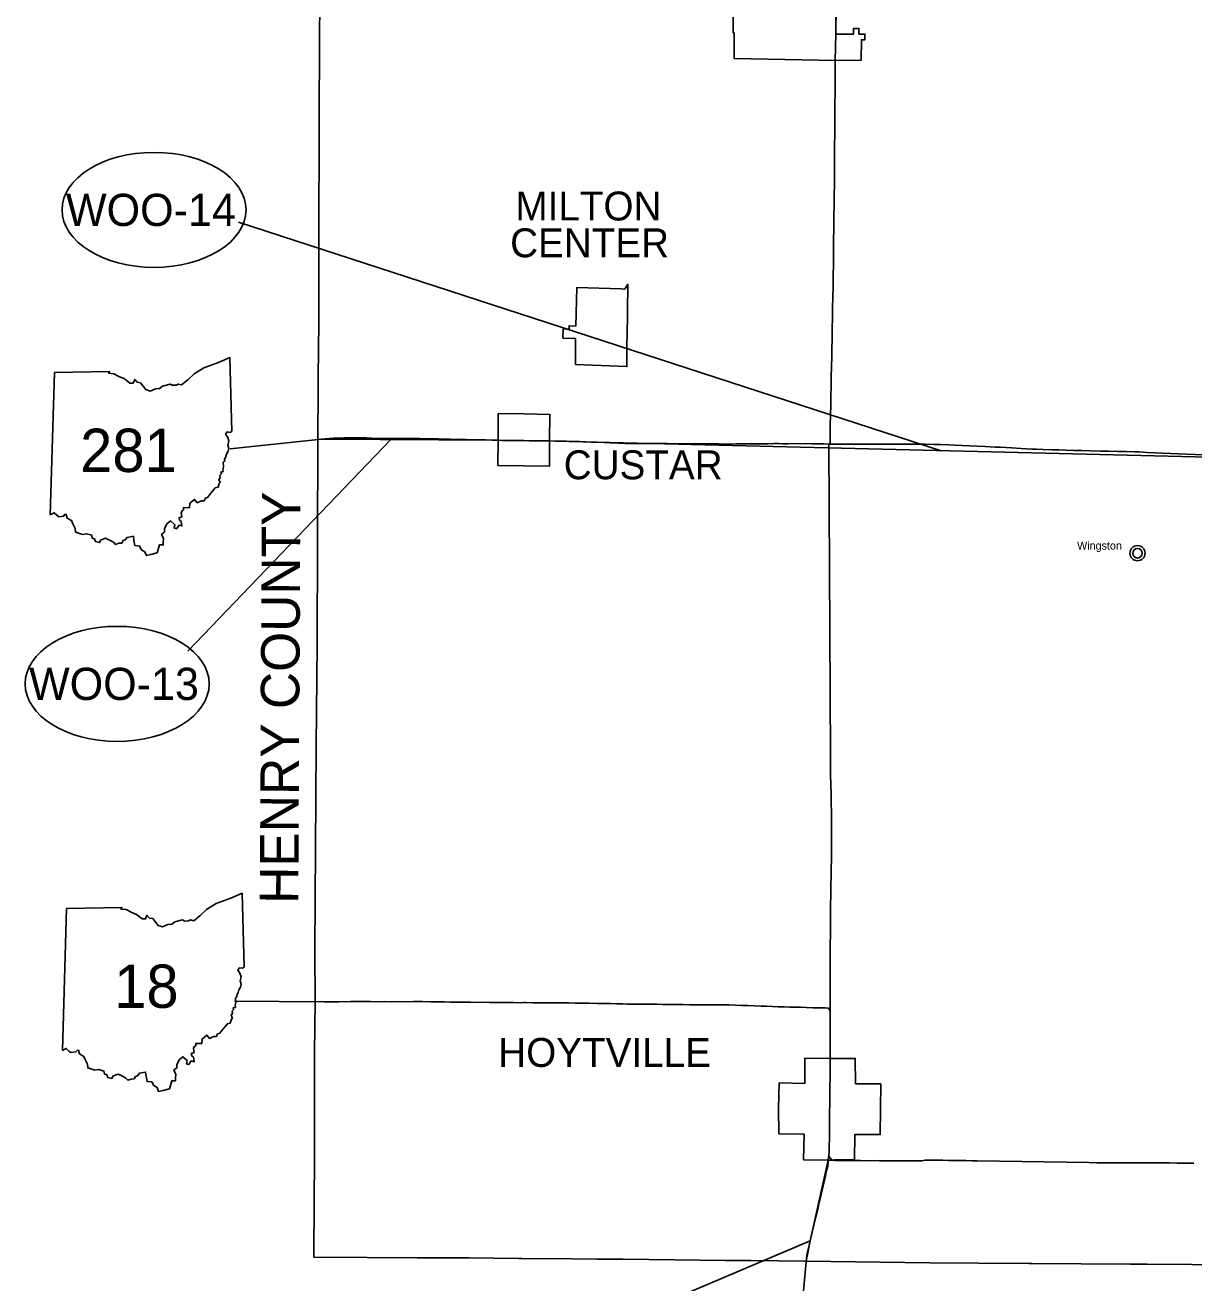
# Model space of a CAD drawing. Extents: x 0 to 851, y 0 to 440.
# Drawn here: x 180.9 to 282.5, y 84.4 to 193.8 of the extents above; entities that cross this region are included whole.
import ezdxf

# ---------------------------------------------------------------- set-up
doc = ezdxf.new("R2010")
doc.units = 0
for name, color, linetype in [('DV_X_Corp_Line', 7, 'Continuous'), ('GM_X_Adjacent_County_Text', 7, 'Continuous'), ('GM_X_Corporation_Text', 7, 'Continuous'), ('GM_X_County', 7, 'Continuous'), ('GM_X_State_Route', 7, 'Continuous'), ('PV_P_Text', 7, 'Continuous'), ('RD_P_Fence', 7, 'Continuous'), ('SH_Data', 7, 'Continuous')]:
    doc.layers.add(name, color=color, linetype=linetype)

msp = doc.modelspace()

# ---------------------------------------------------------------- linework, layer by layer
at = {"layer": 'DV_X_Corp_Line'}
msp.add_lwpolyline([(251.36, 195.22), (251.34, 192.98), (252.2, 192.97), (252.88, 192.97), (252.88, 193.47), (253.35, 193.47), (253.35, 192.97), (253.87, 192.97), (253.87, 192.48), (253.56, 192.48), (253.55, 190.72), (251.32, 190.68), (246.9, 190.76), (242.49, 190.84), (242.51, 193.08), (242.42, 193.08), (242.46, 199.73)], dxfattribs=at)
for points in [[(228.7, 164.24), (228.7, 164.75), (228.7, 165.17), (228.7, 165.75), (228.7, 166.02), (228.69, 166.5), (227.61, 166.54), (227.64, 167.35), (228.14, 167.33), (228.15, 167.61), (228.73, 167.58), (228.81, 170.94), (232.68, 170.82), (232.98, 170.81), (233.26, 171.23), (233.19, 166.54), (233.18, 166.34), (233.17, 164.06)], [(221.95, 155.46), (221.98, 157.7), (221.99, 160), (224.25, 159.96), (226.47, 159.9), (226.45, 157.66), (226.43, 155.4), (224.18, 155.44)], [(246.38, 97.35), (246.35, 99.6), (246.42, 101.78), (248.63, 101.73), (248.65, 103.95), (250.89, 103.92), (253.03, 103.91), (253.05, 101.71), (255.24, 101.7), (255.2, 97.3), (253, 97.31), (252.97, 95.09), (252.52, 95.1), (252.08, 95.1), (251.58, 95.1), (251.28, 95.1), (251.23, 95.11), (251.15, 95.08), (250.74, 95.08), (248.54, 95.11), (248.6, 97.32)]]:
    msp.add_lwpolyline(points, close=True, dxfattribs=at)
for radius in [0.658, 0.417]:
    msp.add_circle((277.57, 147.84), radius, dxfattribs=at)
at = {"layer": 'GM_X_County'}
msp.add_lwpolyline([(286.18, 85.96), (278.4, 86.02), (277.29, 86.03), (276.96, 86.03), (268.38, 86.08), (268.13, 86.08), (263.75, 86.11), (259.48, 86.15), (248.77, 86.3), (243.96, 86.35), (241.7, 86.35), (237.33, 86.41), (232.85, 86.45), (230.6, 86.47), (228.39, 86.49), (224.05, 86.53), (223.76, 86.53), (219.47, 86.57), (214.94, 86.59), (210.58, 86.62), (205.96, 86.64), (205.96, 86.99), (206.01, 95.47), (206, 99.97), (206, 104.43), (206.08, 108.84), (206.03, 113.3), (206.09, 122.17), (206.15, 131.08), (206.23, 139.92), (206.27, 148.79), (206.3, 157.72), (206.37, 166.56), (206.38, 166.88), (206.38, 175.5), (206.38, 175.64), (206.41, 184.56), (206.45, 193.37), (206.48, 194.94)], dxfattribs=at)
at = {"layer": 'GM_X_State_Route'}
for points in [[(251.33, 192.99), (251.33, 193.74), (251.35, 194.49), (251.36, 195.22), (251.36, 195.6), (251.36, 196.41), (251.37, 197.3), (251.38, 198.22), (251.39, 199.02), (251.39, 199.66), (251.39, 199.83)], [(251.28, 190.69), (251.33, 192.99)], [(250.85, 157.33), (250.85, 157.94), (250.86, 158.93), (250.88, 159.84), (250.9, 160.73), (250.91, 161.5), (250.92, 162.36), (250.93, 163.18), (250.96, 164.08), (250.98, 164.92), (251, 165.75), (251.01, 166.24), (251.02, 166.76), (251.03, 167.36), (251.04, 168.32), (251.06, 169.16), (251.07, 170.1), (251.1, 171.04), (251.12, 172), (251.13, 172.91), (251.14, 173.71), (251.15, 174.57), (251.15, 175.15), (251.16, 175.95), (251.18, 177.11), (251.19, 178.08), (251.2, 178.96), (251.21, 179.95), (251.21, 180.98), (251.21, 181.82), (251.22, 182.76), (251.23, 183.5), (251.24, 184.06), (251.28, 190.65), (251.28, 190.69)], [(198.67, 156.91), (206.63, 157.76), (206.95, 157.79), (207.3, 157.81), (207.67, 157.83), (208.11, 157.84), (208.56, 157.86), (208.89, 157.86), (209.48, 157.87), (209.95, 157.87), (210.53, 157.87), (211.4, 157.81), (212.2, 157.81), (212.97, 157.81), (213.76, 157.8), (214.46, 157.8), (215.21, 157.8), (215.82, 157.79), (216.44, 157.77), (216.77, 157.77)], [(216.77, 157.77), (216.93, 157.76), (217.55, 157.75), (217.82, 157.75)], [(217.82, 157.75), (218.07, 157.74), (218.42, 157.74)], [(218.42, 157.74), (218.56, 157.74), (219.21, 157.73), (219.64, 157.71), (219.82, 157.71)], [(219.82, 157.71), (220.26, 157.69), (220.87, 157.69), (221.44, 157.67), (221.9, 157.66), (221.92, 157.66)], [(221.92, 157.66), (221.93, 157.66), (222.32, 157.65), (222.71, 157.65), (222.72, 157.65)], [(222.72, 157.65), (222.74, 157.65), (223.17, 157.64), (223.18, 157.64), (223.66, 157.64), (223.69, 157.64), (224.12, 157.63), (224.12, 157.63)], [(224.12, 157.63), (224.21, 157.63), (224.68, 157.62), (225.22, 157.62), (225.64, 157.61), (226.09, 157.61), (226.3, 157.6), (226.3, 157.6)], [(226.3, 157.6), (226.49, 157.6), (226.97, 157.59), (227.51, 157.58), (227.91, 157.57), (228.46, 157.56), (229.04, 157.54), (229.6, 157.52), (230.08, 157.5), (230.59, 157.48), (231.19, 157.46), (231.72, 157.44), (232.43, 157.42), (233.02, 157.39), (233.64, 157.38), (234.53, 157.38), (235.25, 157.38), (235.95, 157.37), (236.66, 157.37), (237.35, 157.36), (237.96, 157.36), (238.61, 157.36), (239.26, 157.35), (239.93, 157.35), (240.58, 157.34), (241.17, 157.34), (241.76, 157.33), (241.96, 157.33), (242.21, 157.33), (242.65, 157.34), (243.21, 157.34), (243.78, 157.35), (244.29, 157.35), (244.91, 157.36), (245.47, 157.36), (245.98, 157.37), (246.35, 157.37), (246.66, 157.36), (247.17, 157.36), (248.7, 157.37), (249.26, 157.35), (249.77, 157.34), (250.29, 157.34), (250.85, 157.33)], [(250.85, 108.05), (250.86, 108.35), (250.85, 109.1), (250.86, 109.87), (250.85, 110.71), (250.86, 111.38), (250.85, 112.22), (250.85, 112.71), (250.86, 113.85), (250.87, 114.68), (250.88, 115.63), (250.88, 116.45), (250.89, 117.27), (250.9, 118.08), (250.91, 118.97), (250.93, 119.72), (250.94, 120.49), (250.96, 121.21), (250.96, 121.79), (250.97, 122.31), (250.97, 123.15), (250.96, 123.99), (250.96, 124.66), (250.95, 125.38), (250.93, 126.09), (250.92, 126.93), (250.9, 127.76), (250.89, 128.54), (250.88, 129.53), (250.88, 130.21), (250.73, 157.32)], [(250.85, 157.33), (251.35, 157.32), (251.92, 157.33), (252.58, 157.32), (253.12, 157.32), (253.59, 157.32), (254.15, 157.32), (254.72, 157.31), (255.2, 157.32), (255.76, 157.31), (256.3, 157.31), (256.8, 157.31), (257.33, 157.31), (258.03, 157.31), (258.55, 157.31), (259.13, 157.31), (259.93, 157.29)], [(259.93, 157.29), (260.45, 157.28), (261.18, 157.25), (261.69, 157.23), (262.32, 157.2), (263, 157.17), (263.64, 157.14), (264.33, 157.11), (265.19, 157.07), (265.62, 157.05), (266.62, 157), (267.46, 156.94), (267.93, 156.92), (268.38, 156.89), (268.8, 156.88), (269.36, 156.86), (270.18, 156.84), (270.74, 156.82), (271.35, 156.8), (272, 156.78), (272.7, 156.77), (273.43, 156.75), (274.37, 156.72), (275.06, 156.7), (275.82, 156.68), (276.58, 156.67), (277.35, 156.64), (277.72, 156.64), (278.4, 156.61), (279.04, 156.58), (279.69, 156.55), (280.44, 156.52), (291.12, 156.07)], [(250.88, 130.21), (250.88, 130.3), (250.88, 130.66)], [(199.06, 108.88), (206.83, 108.84), (208.15, 108.83), (209.15, 108.85), (209.9, 108.85), (210.42, 108.85), (210.89, 108.85), (211.47, 108.84), (212.13, 108.85), (212.74, 108.84), (213.27, 108.85), (213.88, 108.84), (214.61, 108.85), (215.39, 108.85), (216.11, 108.84), (216.73, 108.83), (217.32, 108.83), (217.84, 108.82), (218.51, 108.82), (219.05, 108.81), (219.58, 108.8), (220.15, 108.79), (220.7, 108.8), (221.22, 108.79), (221.86, 108.78), (222.56, 108.77), (223.31, 108.77), (224.03, 108.76), (224.19, 108.77), (224.38, 108.77), (225.03, 108.76), (225.77, 108.76), (226.15, 108.75), (226.75, 108.74), (227.42, 108.74), (228.12, 108.74), (228.68, 108.73), (229.22, 108.72), (229.89, 108.71), (230.61, 108.7), (230.94, 108.69), (231.19, 108.69), (231.74, 108.68), (232.26, 108.66), (232.81, 108.66), (233.19, 108.64), (233.26, 108.64), (233.84, 108.63), (234.29, 108.63), (234.83, 108.63), (235.32, 108.63), (235.79, 108.62), (236.28, 108.61), (236.89, 108.61), (237.52, 108.6), (238.04, 108.59), (238.65, 108.58), (239.18, 108.58), (239.74, 108.58), (240.21, 108.57), (240.73, 108.57), (241.27, 108.57), (241.74, 108.57), (242.03, 108.56), (242.61, 108.54), (243.15, 108.52), (243.68, 108.51), (244.28, 108.48), (244.83, 108.47), (245.31, 108.45), (245.82, 108.43), (246.33, 108.41), (246.86, 108.4), (247.3, 108.38), (247.75, 108.37), (248.26, 108.36), (248.76, 108.34), (249.35, 108.32), (249.83, 108.31), (250.37, 108.3), (250.64, 108.28), (250.69, 108.27), (250.73, 108.23), (250.79, 108.14), (250.85, 108.05)], [(250.85, 108.05), (250.86, 107.61), (250.86, 107.03), (250.85, 106.46), (250.85, 105.9), (250.86, 105.4), (250.85, 104.94), (250.86, 104.41), (250.86, 103.85)], [(250.85, 102.97), (250.85, 102.75), (250.84, 102.2), (250.83, 101.55), (250.83, 100.94), (250.82, 100.67)], [(250.86, 103.85), (250.86, 103.85), (250.86, 103.33), (250.85, 102.97)], [(250.82, 100.67), (250.82, 100.67), (250.82, 100.64), (250.82, 100.56), (250.81, 100.1), (250.81, 99.98), (250.81, 99.71), (250.8, 99.47), (250.8, 99.44), (250.8, 99.44)], [(250.79, 98.55), (250.79, 98.49), (250.79, 98.4), (250.79, 97.9), (250.78, 97.39), (250.78, 97.23)], [(250.8, 99.44), (250.8, 99.35), (250.79, 98.91), (250.79, 98.55)], [(250.78, 97.23), (250.78, 97.23), (250.78, 96.86), (250.77, 96.33), (250.76, 96.06), (250.75, 95.85), (250.72, 95.47)], [(248.09, 79.05), (248.82, 86.84), (248.96, 87.39), (249.11, 88.06), (249.29, 88.82), (249.45, 89.52), (249.59, 90.14), (249.76, 90.82), (249.9, 91.43), (250.05, 92.09), (250.23, 92.85), (250.4, 93.57), (250.54, 94.16), (250.63, 94.54), (250.64, 94.64), (250.66, 94.81), (250.68, 95.06), (250.72, 95.47)], [(250.72, 95.47), (250.79, 95.34), (250.85, 95.25), (250.92, 95.18), (250.99, 95.12), (251.06, 95.06), (251.23, 95.05)], [(251.23, 95.05), (251.58, 95.04), (252.08, 95.04), (252.1, 95.04), (252.11, 95.04)], [(252.11, 95.04), (252.58, 95.04), (252.98, 95.04), (252.98, 95.04)], [(252.98, 95.04), (253.01, 95.04), (253.49, 95.03), (253.98, 95), (254.61, 95.04), (255.13, 95.02), (255.56, 95.02), (256.05, 95.02), (256.45, 95.01), (256.86, 95.02), (257.38, 95.02), (257.94, 95.02), (258.47, 95.01), (258.72, 95.01), (258.82, 95.02), (258.96, 95.05), (259.09, 95.07), (259.2, 95.07), (259.57, 95.06), (260.12, 95.06), (260.65, 95.06), (261.15, 95.05), (261.64, 95.04), (262.12, 95.03), (262.65, 95.03), (263.16, 95.02), (263.62, 95.01), (275.27, 94.84)], [(274.04, 94.85), (274.64, 94.85), (275.27, 94.84), (275.93, 94.84), (276.62, 94.85), (277.31, 94.85)], [(277.31, 94.85), (277.92, 94.85), (278.59, 94.85), (279.18, 94.84), (279.75, 94.83), (280.34, 94.83), (281.02, 94.82), (281.57, 94.81), (282.46, 94.81)]]:
    msp.add_lwpolyline(points, dxfattribs=at)
at = {"layer": 'PV_P_Text'}
for p, q in [((183.04, 151.18), (183.39, 163.55)), ((183.04, 151.18), (183.39, 163.55)), ((184.11, 104.59), (184.46, 116.96)), ((184.11, 104.59), (184.46, 116.96))]:
    msp.add_line(p, q, dxfattribs=at)
for points in [[(183.39, 163.55), (188.19, 163.63), (188.11, 163.48), (188.57, 163.45), (189.05, 163.18), (189.45, 163.02), (189.95, 162.62), (190.25, 162.63), (190.38, 162.95), (190.6, 162.7), (190.88, 162.66), (191.34, 162.07), (191.73, 161.94), (192.19, 162.14), (192.54, 162.17), (192.79, 162.37), (193.45, 162.55), (193.63, 162.44), (193.98, 162.46), (194.16, 162.54), (194.46, 162.47), (195, 162.92), (195.55, 163.45), (196.4, 163.95), (197.66, 164.43), (198.66, 164.85), (198.81, 158.43)], [(183.39, 163.55), (188.19, 163.63), (188.11, 163.48), (188.57, 163.45), (189.05, 163.18), (189.45, 163.02), (189.95, 162.62), (190.25, 162.63), (190.38, 162.95), (190.6, 162.7), (190.88, 162.66), (191.34, 162.07), (191.73, 161.94), (192.19, 162.14), (192.54, 162.17), (192.79, 162.37), (193.45, 162.55), (193.63, 162.44), (193.98, 162.46), (194.16, 162.54), (194.46, 162.47), (195, 162.92), (195.55, 163.45), (196.4, 163.95), (197.66, 164.43), (198.66, 164.85), (198.81, 158.43)], [(198.81, 158.43), (198.66, 158.34), (198.43, 158.38), (198.28, 158.2), (198.47, 157.9), (198.56, 157.58), (198.48, 157.23), (198.56, 156.95), (198.5, 156.7), (198.36, 156.46), (198.31, 156.24), (198.19, 155.99), (198.2, 155.86), (198.08, 155.75), (198.1, 155.35), (198.04, 155.13), (198.06, 154.94), (197.87, 154.89), (197.91, 154.73), (197.79, 154.6), (197.82, 154.39), (197.68, 154.26), (197.82, 153.99), (197.71, 153.9), (197.62, 153.58), (197.38, 153.51), (196.89, 152.91), (196.72, 152.68), (196.52, 152.63), (196.42, 152.4), (196.18, 152.39), (195.82, 152.23), (195.58, 152.51), (195.17, 152.18), (195.13, 151.79), (194.61, 151.8), (194.63, 151.61), (194.52, 151.55), (194.41, 151.36), (194.47, 151.01), (194.23, 150.92), (194.26, 150.72), (194.41, 150.6), (194.48, 150.21), (194.23, 150.29), (194.02, 149.96), (193.8, 150.04), (193.87, 150.31), (193.5, 150.65), (193.16, 150.38), (192.98, 149.96), (192.98, 149.67), (192.72, 149.5), (192.88, 149.1), (192.85, 148.82), (192.86, 148.56), (192.54, 148.57), (192.34, 147.86)], [(198.81, 158.43), (198.66, 158.34), (198.43, 158.38), (198.28, 158.2), (198.47, 157.9), (198.56, 157.58), (198.48, 157.23), (198.56, 156.95), (198.5, 156.7), (198.36, 156.46), (198.31, 156.24), (198.19, 155.99), (198.2, 155.86), (198.08, 155.75), (198.1, 155.35), (198.04, 155.13), (198.06, 154.94), (197.87, 154.89), (197.91, 154.73), (197.79, 154.6), (197.82, 154.39), (197.68, 154.26), (197.82, 153.99), (197.71, 153.9), (197.62, 153.58), (197.38, 153.51), (196.89, 152.91), (196.72, 152.68), (196.52, 152.63), (196.42, 152.4), (196.18, 152.39), (195.82, 152.23), (195.58, 152.51), (195.17, 152.18), (195.13, 151.79), (194.61, 151.8), (194.63, 151.61), (194.52, 151.55), (194.41, 151.36), (194.47, 151.01), (194.23, 150.92), (194.26, 150.72), (194.41, 150.6), (194.48, 150.21), (194.23, 150.29), (194.02, 149.96), (193.8, 150.04), (193.87, 150.31), (193.5, 150.65), (193.16, 150.38), (192.98, 149.96), (192.98, 149.67), (192.72, 149.5), (192.88, 149.1), (192.85, 148.82), (192.86, 148.56), (192.54, 148.57), (192.34, 147.86)], [(192.34, 147.86), (191.78, 147.72), (191.39, 147.64), (191.25, 147.96), (190.98, 148.13), (190.8, 148.46), (190.4, 148.5), (190.3, 148.95), (190.26, 149.31), (189.71, 149.22), (189.56, 149), (189.37, 148.94), (189.26, 148.72), (188.99, 148.7), (188.71, 148.59), (188.52, 148.81), (188.06, 149.03), (187.85, 149.14), (187.41, 148.97), (187.32, 148.76), (186.97, 148.85), (186.89, 149.08), (186.68, 149.15), (186.64, 149.4), (186.19, 149.53), (185.84, 149.48), (185.24, 149.68), (185.2, 150), (184.99, 150.4), (184.89, 150.67), (184.5, 150.88), (184.43, 151.21), (184.3, 151.2), (184.19, 151.06), (183.77, 151), (183.6, 151.14), (183.36, 151.36), (183.04, 151.18)], [(192.34, 147.86), (191.78, 147.72), (191.39, 147.64), (191.25, 147.96), (190.98, 148.13), (190.8, 148.46), (190.4, 148.5), (190.3, 148.95), (190.26, 149.31), (189.71, 149.22), (189.56, 149), (189.37, 148.94), (189.26, 148.72), (188.99, 148.7), (188.71, 148.59), (188.52, 148.81), (188.06, 149.03), (187.85, 149.14), (187.41, 148.97), (187.32, 148.76), (186.97, 148.85), (186.89, 149.08), (186.68, 149.15), (186.64, 149.4), (186.19, 149.53), (185.84, 149.48), (185.24, 149.68), (185.2, 150), (184.99, 150.4), (184.89, 150.67), (184.5, 150.88), (184.43, 151.21), (184.3, 151.2), (184.19, 151.06), (183.77, 151), (183.6, 151.14), (183.36, 151.36), (183.04, 151.18)], [(184.46, 116.96), (189.26, 117.04), (189.18, 116.9), (189.63, 116.86), (190.12, 116.6), (190.52, 116.43), (191.02, 116.04), (191.32, 116.04), (191.44, 116.37), (191.67, 116.12), (191.94, 116.07), (192.41, 115.48), (192.8, 115.35), (193.26, 115.56), (193.61, 115.59), (193.86, 115.79), (194.52, 115.96), (194.7, 115.86), (195.05, 115.88), (195.22, 115.95), (195.53, 115.89), (196.06, 116.34), (196.62, 116.87), (197.46, 117.37), (198.73, 117.84), (199.73, 118.27), (199.88, 111.85)], [(184.46, 116.96), (189.26, 117.04), (189.18, 116.9), (189.63, 116.86), (190.12, 116.6), (190.52, 116.43), (191.02, 116.04), (191.32, 116.04), (191.44, 116.37), (191.67, 116.12), (191.94, 116.07), (192.41, 115.48), (192.8, 115.35), (193.26, 115.56), (193.61, 115.59), (193.86, 115.79), (194.52, 115.96), (194.7, 115.86), (195.05, 115.88), (195.22, 115.95), (195.53, 115.89), (196.06, 116.34), (196.62, 116.87), (197.46, 117.37), (198.73, 117.84), (199.73, 118.27), (199.88, 111.85)], [(199.88, 111.85), (199.73, 111.76), (199.5, 111.8), (199.34, 111.62), (199.53, 111.32), (199.63, 111), (199.55, 110.65), (199.62, 110.36), (199.57, 110.12), (199.43, 109.88), (199.38, 109.65), (199.25, 109.41), (199.26, 109.27), (199.15, 109.17), (199.17, 108.77), (199.11, 108.54), (199.13, 108.35), (198.94, 108.3), (198.98, 108.14), (198.86, 108.02), (198.89, 107.81), (198.75, 107.67), (198.88, 107.4), (198.78, 107.32), (198.69, 106.99), (198.44, 106.93), (197.96, 106.33), (197.78, 106.1), (197.59, 106.04), (197.48, 105.81), (197.24, 105.81), (196.88, 105.65), (196.65, 105.93), (196.24, 105.59), (196.2, 105.21), (195.68, 105.22), (195.7, 105.02), (195.58, 104.97), (195.48, 104.77), (195.54, 104.42), (195.3, 104.34), (195.33, 104.13), (195.48, 104.01), (195.55, 103.63), (195.29, 103.7), (195.08, 103.38), (194.87, 103.45), (194.94, 103.73), (194.57, 104.06), (194.23, 103.8), (194.05, 103.37), (194.04, 103.09), (193.79, 102.92), (193.95, 102.51), (193.92, 102.24), (193.93, 101.97), (193.6, 101.98), (193.41, 101.27)], [(199.88, 111.85), (199.73, 111.76), (199.5, 111.8), (199.34, 111.62), (199.53, 111.32), (199.63, 111), (199.55, 110.65), (199.62, 110.36), (199.57, 110.12), (199.43, 109.88), (199.38, 109.65), (199.25, 109.41), (199.26, 109.27), (199.15, 109.17), (199.17, 108.77), (199.11, 108.54), (199.13, 108.35), (198.94, 108.3), (198.98, 108.14), (198.86, 108.02), (198.89, 107.81), (198.75, 107.67), (198.88, 107.4), (198.78, 107.32), (198.69, 106.99), (198.44, 106.93), (197.96, 106.33), (197.78, 106.1), (197.59, 106.04), (197.48, 105.81), (197.24, 105.81), (196.88, 105.65), (196.65, 105.93), (196.24, 105.59), (196.2, 105.21), (195.68, 105.22), (195.7, 105.02), (195.58, 104.97), (195.48, 104.77), (195.54, 104.42), (195.3, 104.34), (195.33, 104.13), (195.48, 104.01), (195.55, 103.63), (195.29, 103.7), (195.08, 103.38), (194.87, 103.45), (194.94, 103.73), (194.57, 104.06), (194.23, 103.8), (194.05, 103.37), (194.04, 103.09), (193.79, 102.92), (193.95, 102.51), (193.92, 102.24), (193.93, 101.97), (193.6, 101.98), (193.41, 101.27)], [(193.41, 101.27), (192.85, 101.14), (192.46, 101.05), (192.32, 101.38), (192.04, 101.55), (191.86, 101.87), (191.46, 101.92), (191.37, 102.36), (191.32, 102.72), (190.78, 102.64), (190.63, 102.41), (190.44, 102.35), (190.32, 102.13), (190.06, 102.11), (189.78, 102.01), (189.59, 102.23), (189.13, 102.45), (188.92, 102.56), (188.48, 102.38), (188.39, 102.17), (188.04, 102.27), (187.96, 102.5), (187.75, 102.57), (187.7, 102.82), (187.25, 102.95), (186.91, 102.89), (186.3, 103.09), (186.27, 103.42), (186.06, 103.81), (185.95, 104.09), (185.57, 104.3), (185.49, 104.62), (185.37, 104.61), (185.26, 104.48), (184.83, 104.42), (184.66, 104.55), (184.42, 104.78), (184.11, 104.59)], [(193.41, 101.27), (192.85, 101.14), (192.46, 101.05), (192.32, 101.38), (192.04, 101.55), (191.86, 101.87), (191.46, 101.92), (191.37, 102.36), (191.32, 102.72), (190.78, 102.64), (190.63, 102.41), (190.44, 102.35), (190.32, 102.13), (190.06, 102.11), (189.78, 102.01), (189.59, 102.23), (189.13, 102.45), (188.92, 102.56), (188.48, 102.38), (188.39, 102.17), (188.04, 102.27), (187.96, 102.5), (187.75, 102.57), (187.7, 102.82), (187.25, 102.95), (186.91, 102.89), (186.3, 103.09), (186.27, 103.42), (186.06, 103.81), (185.95, 104.09), (185.57, 104.3), (185.49, 104.62), (185.37, 104.61), (185.26, 104.48), (184.83, 104.42), (184.66, 104.55), (184.42, 104.78), (184.11, 104.59)]]:
    msp.add_lwpolyline(points, dxfattribs=at)
at = {"layer": 'RD_P_Fence'}
for p, q in [((206.63, 157.76), (221.92, 157.66)), ((226.97, 157.59), (313.35, 155.44))]:
    msp.add_line(p, q, dxfattribs=at)
msp.add_lwpolyline([(248.77, 86.3), (249.11, 88.06), (250.68, 95.06)], dxfattribs=at)
at = {"layer": 'SH_Data'}
for p, q in [((199.39, 176.63), (260.49, 156.75)), ((195.01, 139.33), (212.66, 157.72)), ((228.61, 79.37), (249.11, 88.06))]:
    msp.add_line(p, q, dxfattribs=at)
for centre in [(192.06, 177.69), (188.85, 136.48)]:
    msp.add_ellipse(centre, major_axis=(8, 0), ratio=0.625, dxfattribs=at)

# ---------------------------------------------------------------- texts
at = {"layer": 'DV_X_Corp_Line'}
msp.add_text('Wingston', height=0.698, rotation=0, dxfattribs=at).set_placement((272.32, 148.15))
at = {"layer": 'GM_X_Adjacent_County_Text'}
msp.add_text('HENRY COUNTY', height=3.35, rotation=89.7009, dxfattribs=at).set_placement((204.6, 117.35))
at = {"layer": 'GM_X_Corporation_Text'}
for s, p in [('MILTON', (223.48, 176.77)), ('CENTER', (223.02, 173.57)), ('CUSTAR', (227.68, 154.27)), ('HOYTVILLE', (221.99, 103.18))]:
    msp.add_text(s, height=2.513, rotation=0, dxfattribs=at).set_placement(p)
at = {"layer": 'PV_P_Text'}
for s, p in [('281', (185.63, 154.9)), ('18', (188.59, 108.31))]:
    msp.add_text(s, height=3.769, dxfattribs=at).set_placement(p)
at = {"layer": 'SH_Data'}
for s, p in [('WOO-14', (184.4, 176.29)), ('WOO-13', (181.19, 135.08))]:
    msp.add_text(s, height=2.8, dxfattribs=at).set_placement(p)

doc.saveas('drawing.dxf')
